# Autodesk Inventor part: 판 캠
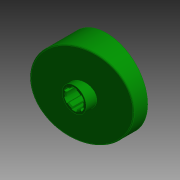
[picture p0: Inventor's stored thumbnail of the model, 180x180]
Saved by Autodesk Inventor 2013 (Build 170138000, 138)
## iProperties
Created: 2021-07
Part Number: 판 캠
Document SubType Name: 모델링
Designer: mdu
Material: 알루미늄 6061
Density: 2.71 g/cm^3
Mass: 235.299 g
Surface Area: 331.301 cm^2
Volume: 86.8262 cm^3
변환 표준: STEP AP214IS
파일 이름: C:\Users\SeoGD\Desktop\?쒗뿕\??stp
전처리기: Build: 253, Release: 2010 SP1 - Date: Wed 07/29/2009
전송 단위: 밀리미터
불확실성: 0.01
Author: mdu
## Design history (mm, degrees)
node "작업 평면4"
sketch "스케치1"
  geometry: C1 r 44.5 at (0, 0); 1 further point
  constraints: 1 centre point, 1 coincident
  dimensions: "d25" = 89 diameter of C1
extrude "돌출1" new body sketch "스케치1" distance "d1" = 40; taper "d2" = 0 deg
sketch "스케치2"
  geometry: L1 (-44.5, 15)-(44.5, 38.847); L2 (-44.5, 0)-(-44.5, 40) reference; L3 (-44.5, 40)-(44.5, 40) reference; L4 (44.5, 0)-(44.5, 40) reference; 1 further point
  constraints: 2 end point, 2 point on line
  dimensions: "d26" = 15 distance of L2.start L1.start; "d27" = 75 deg angle of L1 L2
extrude "돌출2" cut sketch "스케치2" stored distance "d5" = 40; taper "d6" = 0 deg
node "작업 평면1"
sketch "스케치3"
  geometry: C1 r 13 at (0, 0); 1 further point
  constraints: 1 centre point, 1 coincident
  dimensions: "d9" = 26 diameter of C1
extrude "돌출3" join sketch "스케치3" distance "d10" = 38; taper "d11" = 0 deg
hole "구멍1" diameter "d14" = 18; stored, may be unused: countersink angle "d18" = 90 deg, drill point angle "d20" = 118 deg; dims "d12" = 10, "d13" = 10, "d15" = 6, "d16" = 4, "d17" = 2, "d19" = 8
feature "쉘2" dims "d29" = 5
sketch "스케치6"
  geometry: C1 r 17.5 at (0, 0); C2 r 14 at (0, 0) reference; 1 further point
  constraints: 1 centre point, 1 coincident
  dimensions: "d28" = 35 diameter of C1
extrude "돌출4" join sketch "스케치6" stored distance "d30" = 38; taper "d31" = 0 deg
fillet "모깎기1" dims "d32" = 3
chamfer "모따기1" distance "d21" = 1; stored, may be unused: second distance "d22" = 2, angle "d23" = 45 deg
sketch "스케치7"
  geometry: L1 (-12.374, 12.374)-(-27.931, 27.931); A1 r 39.5 centre (0, 0) between (-27.931, 27.931) and (0, 39.5) reference; 2 further points
  constraints: 2 end point, 2 point on circle, 1 point on line, 1 vertical alignment, 2 other
  dimensions: "d33" = 45 deg dimension on point (0, 0) L1.start A1.end
feature "리브1" sketch "스케치7" dims "d34" = 5, "d35" = 1, "d36" = 0
fillet "모깎기2" dims "d37" = 3
sketch "스케치8"
  geometry: L1 (2.5, 10.712)-(2.5, 8.646); L2 (-2.5, 10.712)-(-2.5, 8.646); A1 r 11 centre (0, 0) between (2.5, 10.712) and (-2.5, 10.712); A2 r 9 centre (0, 0) between (2.5, 8.646) and (-2.5, 8.646) reference; 1 further point
  constraints: 4 end point, 4 point on circle, 2 parallel, 1 centre point, 1 coincident, 1 vertical
  dimensions: "d41" = 22 diameter of A1; "d42" = 5 distance between parallel lines of L1 L2
extrude "돌출5" cut sketch "스케치8" stored distance "d43" = 38; taper "d44" = 0 deg
fillet "모깎기3" dims "d48" = 1
node "솔리드1"
node "솔리드 본체"
node "곡면 본체"
pattern_circular "원형 패턴1" dims angle "d39" = 360 deg
pattern_circular "원형 패턴2" dims angle "d46" = 360 deg
node "솔리드2"
